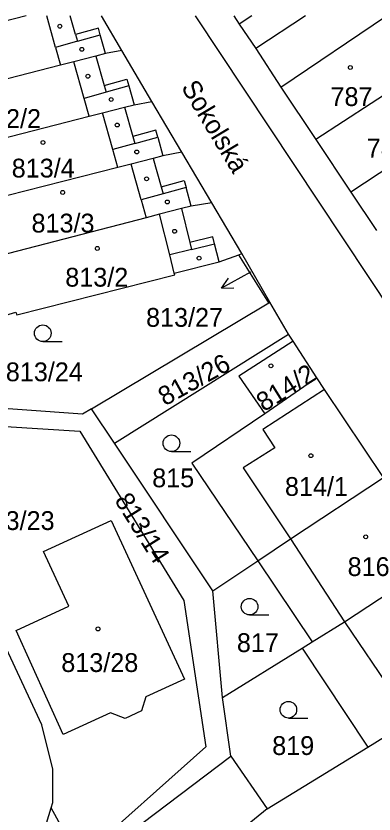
# Model space of a CAD drawing. Extents: x -776606 to -776076, y -974328 to -973875.
# Drawn here: x -776303.5 to -776271.1, y -973946.7 to -973874.5 of the extents above; entities that cross this region are included whole.
import ezdxf

# ---------------------------------------------------------------- set-up
doc = ezdxf.new("R2010")
doc.units = 0
for name, color, linetype in [('Hranice parcel', 7, 'Continuous'), ('Parcelní čísla', 7, 'Continuous'), ('Pop  PČ popisy', 7, 'Continuous'), ('Vnitřní kresba', 7, 'Continuous'), ('Značky budov', 7, 'Continuous'), ('Značky kultur', 7, 'Continuous')]:
    doc.layers.add(name, color=color, linetype=linetype)

msp = doc.modelspace()

# ---------------------------------------------------------------- linework, layer by layer
at = {"layer": 'Hranice parcel'}
for p, q in [((-776293.91, -973877.67), (-776295.761, -973874.542)), ((-776277.343, -973874.542), (-776281.82, -973877.48)), ((-776291.2, -973882.26), (-776293.91, -973877.67)), ((-776288.49, -973886.85), (-776291.2, -973882.26)), ((-776285.78, -973891.43), (-776288.49, -973886.85)), ((-776283.07, -973896.02), (-776285.78, -973891.43)), ((-776283.35, -973896.13), (-776283.07, -973896.02)), ((-776280.64, -973900.45), (-776283.35, -973896.13)), ((-776280.55, -973900.39), (-776283.07, -973896.02)), ((-776296.67, -973910.04), (-776280.64, -973900.45)), ((-776280.55, -973900.39), (-776280.64, -973900.45)), ((-776278.87, -973903.3), (-776280.55, -973900.39)), ((-776294.6, -973913.15), (-776278.87, -973903.3)), ((-776278.46, -973903.93), (-776278.87, -973903.3)), ((-776276.31, -973907.24), (-776278.46, -973903.93)), ((-776276.31, -973907.24), (-776281, -973910.5)), ((-776294.6, -973913.15), (-776296.67, -973910.04)), ((-776285.7, -973926.49), (-776294.6, -973913.15)), ((-776285.7, -973926.49), (-776281.65, -973923.77)), ((-776281.65, -973923.77), (-776276.73, -973931.11)), ((-776284.82, -973936.13), (-776285.7, -973926.49)), ((-776284.82, -973936.13), (-776277.63, -973931.67)), ((-776277.63, -973931.67), (-776276.73, -973931.11)), ((-776277.63, -973931.67), (-776271.71, -973940.6)), ((-776284.08, -973941.43), (-776284.82, -973936.13)), ((-776280.81, -973946.19), (-776271.71, -973940.6)), ((-776297.88, -973951.84), (-776284.08, -973941.43)), ((-776284.08, -973941.43), (-776280.81, -973946.19))]:
    msp.add_line(p, q, dxfattribs=at)
for points in [[(-776302.554, -973874.542), (-776315.23, -973877.79), (-776316.44, -973878.1)], [(-776283.795, -973874.542), (-776283.32, -973875.27), (-776281.82, -973877.48)], [(-776262.79, -973876.85), (-776266.42, -973879.21), (-776276.39, -973885.7)], [(-776281.82, -973877.48), (-776279.55, -973880.99), (-776276.39, -973885.7)], [(-776293.91, -973877.67), (-776295.39, -973877.94), (-776296.26, -973878.17), (-776298.25, -973878.68), (-776299.46, -973878.99), (-776312.67, -973882.4), (-776313.88, -973882.71)], [(-776311.32, -973887.32), (-776310.11, -973887.01), (-776296.87, -973883.61), (-776295.66, -973883.3), (-776293.67, -973882.79), (-776292.8, -973882.57), (-776291.2, -973882.26)], [(-776276.39, -973885.7), (-776273.25, -973890.47), (-776270.91, -973893.94)], [(-776288.49, -973886.85), (-776290.21, -973887.19), (-776291.08, -973887.42), (-776293.07, -973887.92), (-776294.28, -973888.23), (-776307.56, -973891.6), (-776308.77, -973891.91)], [(-776285.78, -973891.43), (-776287.65, -973891.72), (-776288.53, -973891.95), (-776290.51, -973892.46), (-776291.72, -973892.77), (-776305, -973896.22), (-776306.21, -973896.53)], [(-776306.21, -973896.53), (-776304.69, -973901.67), (-776303.49, -973901.31), (-776303.42, -973901.55), (-776289.15, -973897.92), (-776289.19, -973897.77), (-776285.12, -973896.75), (-776283.35, -973896.13)], [(-776296.67, -973910.04), (-776297.47, -973910.52), (-776313.43, -973909.38), (-776317.81, -973900.05)], [(-776278.46, -973903.93), (-776283.35, -973907.1), (-776281, -973910.5)], [(-776270.29, -973916.24), (-776275.61, -973908.29), (-776276.31, -973907.24)], [(-776281, -973910.5), (-776287.6, -973914.95), (-776281.65, -973923.77)], [(-776313.98, -973911.05), (-776297.73, -973912.06), (-776288.32, -973927.36), (-776286.35, -973940.59), (-776297.76, -973950.76), (-776300.32, -973946.11)], [(-776300.32, -973946.11), (-776300.17, -973945.61), (-776300.17, -973942.61), (-776301.14, -973938.61), (-776308.59, -973922.66), (-776313.98, -973911.05)], [(-776281.65, -973923.77), (-776278.7, -973921.8), (-776270.29, -973916.24)], [(-776292.14, -973937.33), (-776293.62, -973938.02), (-776294.94, -973937.52), (-776299.21, -973939.46), (-776303.48, -973930.07), (-776298.72, -973927.88), (-776300.99, -973922.93), (-776294.9, -973920.12), (-776288.27, -973934.48), (-776291.77, -973936.07), (-776292.14, -973937.33)], [(-776276.73, -973931.11), (-776273.8, -973929.3), (-776265.39, -973923.75)], [(-776271.71, -973940.6), (-776267.81, -973938.2), (-776265.38, -973941.82), (-776260.46, -973938.49), (-776261.64, -973936.79), (-776258.19, -973934.5)], [(-776295.13, -973981.83), (-776296.49, -973980.88), (-776298.45, -973978.83), (-776303.97, -973969.66), (-776305.82, -973965.81), (-776306.81, -973961.85), (-776306.08, -973958.37), (-776304.57, -973954.89), (-776301.44, -973949.87), (-776300.32, -973946.11)], [(-776280.81, -973946.19), (-776284.56, -973949.27), (-776282.89, -973951.76)]]:
    msp.add_lwpolyline(points, dxfattribs=at)
at = {"layer": 'Pop  PČ popisy'}
for p, q in [((-776282.31, -973897.69), (-776284.935, -973899.145)), ((-776282.28, -973897.67), (-776282.31, -973897.69)), ((-776284.935, -973899.145), (-776284.302, -973898.221)), ((-776284.935, -973899.145), (-776283.816, -973899.097))]:
    msp.add_line(p, q, dxfattribs=at)
at = {"layer": 'Vnitřní kresba'}
for p, q in [((-776299.91, -973877.38), (-776300.706, -973874.542)), ((-776298.11, -973876.21), (-776298.575, -973874.542)), ((-776236.59, -973950.99), (-776287.263, -973874.542)), ((-776282.184, -973874.542), (-776283.32, -973875.27)), ((-776279.55, -973880.99), (-776270.008, -973874.542)), ((-776296.04, -973875.63), (-776298.11, -973876.21)), ((-776295.87, -973876.25), (-776296.04, -973875.63)), ((-776297.94, -973876.83), (-776299.91, -973877.38)), ((-776298.11, -973876.21), (-776297.94, -973876.83)), ((-776297.94, -973876.83), (-776295.87, -973876.25)), ((-776295.39, -973877.94), (-776295.87, -973876.25)), ((-776299.91, -973877.38), (-776299.46, -973878.99)), ((-776296.26, -973878.17), (-776295.52, -973880.82)), ((-776297.32, -973882), (-776298.25, -973878.68)), ((-776295.52, -973880.82), (-776293.46, -973880.24)), ((-776293.46, -973880.24), (-776293.28, -973880.86)), ((-776295.52, -973880.82), (-776295.35, -973881.44)), ((-776293.28, -973880.86), (-776295.35, -973881.44)), ((-776293.28, -973880.86), (-776292.8, -973882.57)), ((-776295.35, -973881.44), (-776297.32, -973882)), ((-776296.87, -973883.61), (-776297.32, -973882)), ((-776294.73, -973886.62), (-776295.66, -973883.3)), ((-776293.67, -973882.79), (-776292.93, -973885.44)), ((-776263.44, -973884), (-776273.25, -973890.47)), ((-776290.86, -973884.86), (-776292.93, -973885.44)), ((-776292.93, -973885.44), (-776292.75, -973886.07)), ((-776292.75, -973886.07), (-776290.68, -973885.48)), ((-776290.68, -973885.48), (-776290.86, -973884.86)), ((-776290.68, -973885.48), (-776290.21, -973887.19)), ((-776292.75, -973886.07), (-776294.73, -973886.62)), ((-776294.28, -973888.23), (-776294.73, -973886.62)), ((-776291.08, -973887.42), (-776290.37, -973889.98)), ((-776292.17, -973891.16), (-776293.07, -973887.92)), ((-776290.37, -973889.98), (-776288.3, -973889.41)), ((-776288.3, -973889.41), (-776288.12, -973890.04)), ((-776290.37, -973889.98), (-776290.19, -973890.61)), ((-776288.12, -973890.04), (-776290.19, -973890.61)), ((-776287.65, -973891.72), (-776288.12, -973890.04)), ((-776290.19, -973890.61), (-776292.17, -973891.16)), ((-776292.17, -973891.16), (-776291.72, -973892.77)), ((-776288.53, -973891.95), (-776287.78, -973895.02)), ((-776289.6, -973896.14), (-776290.51, -973892.46)), ((-776285.71, -973894.5), (-776287.78, -973895.02)), ((-776285.55, -973895.13), (-776285.71, -973894.5)), ((-776287.62, -973895.64), (-776289.6, -973896.14)), ((-776287.78, -973895.02), (-776287.62, -973895.64)), ((-776287.62, -973895.64), (-776285.55, -973895.13)), ((-776285.12, -973896.75), (-776285.55, -973895.13)), ((-776289.19, -973897.77), (-776289.6, -973896.14)), ((-776275.61, -973908.29), (-776281.18, -973911.9)), ((-776281.18, -973911.9), (-776280.1, -973913.58)), ((-776280.1, -973913.58), (-776282.95, -973915.38)), ((-776282.95, -973915.38), (-776278.7, -973921.8)), ((-776278.7, -973921.8), (-776273.8, -973929.3)), ((-776273.8, -973929.3), (-776267.81, -973938.2))]:
    msp.add_line(p, q, dxfattribs=at)
at = {"layer": 'Značky budov'}
for centre in [(-776299.527, -973875.469), (-776297.537, -973877.559), (-776273.287, -973879.199), (-776296.987, -973879.989), (-776294.887, -973882.089), (-776294.337, -973884.399), (-776301.047, -973885.979), (-776292.577, -973886.829), (-776291.687, -973889.259), (-776299.267, -973890.489), (-776289.817, -973891.349), (-776289.157, -973893.999), (-776296.137, -973895.549), (-776286.947, -973896.429), (-776280.457, -973906.159), (-776276.847, -973914.279), (-776271.897, -973921.609), (-776296.077, -973929.929)]:
    msp.add_circle(centre, 0.175, dxfattribs=at)
at = {"layer": 'Značky kultur'}
for p, q in [((-776301.063, -973903.96), (-776299.313, -973903.96)), ((-776289.443, -973913.9), (-776287.693, -973913.9)), ((-776282.383, -973928.67), (-776280.633, -973928.67)), ((-776278.883, -973937.98), (-776277.133, -973937.98))]:
    msp.add_line(p, q, dxfattribs=at)
for centre in [(-776301.063, -973903.21), (-776289.443, -973913.15), (-776282.383, -973927.92), (-776278.883, -973937.23)]:
    msp.add_circle(centre, 0.75, dxfattribs=at)

# ---------------------------------------------------------------- texts
at = {"layer": 'Parcelní čísla'}
for s, p in [('787', (-776275.08, -973882.68)), ('812/2', (-776306.91, -973884.66)), ('785', (-776271.81, -973887.34)), ('813/4', (-776303.87, -973889.14)), ('813/3', (-776302.08, -973894.11)), ('813/2', (-776299.03, -973899)), ('813/27', (-776291.735, -973902.628)), ('813/24', (-776304.4, -973907.55)), ('815', (-776291.18, -973917.13)), ('814/1', (-776279.19, -973917.91)), ('813/23', (-776306.95, -973920.99)), ('816', (-776273.53, -973925.15)), ('817', (-776283.53, -973932.02)), ('813/28', (-776299.39, -973933.82)), ('819', (-776280.34, -973941.32))]:
    msp.add_text(s, height=1.7, dxfattribs=at).set_placement(p)
for s, rotation, p in [('813/26', 29, (-776290.037, -973909.823)), ('814/2', 32, (-776281.089, -973910.35)), ('813/14', 302, (-776294.63, -973918.31))]:
    msp.add_text(s, height=1.7, rotation=rotation, dxfattribs=at).set_placement(p)
at = {"layer": 'Pop  PČ popisy'}
msp.add_text('Sokolská', height=1.7, rotation=301, dxfattribs=at).set_placement((-776288.608, -973880.987))

doc.saveas('drawing.dxf')
